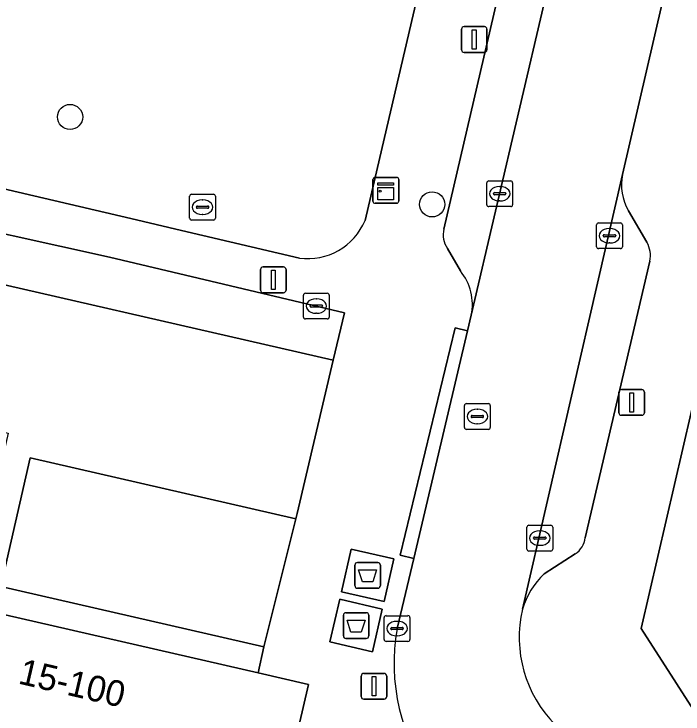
# Model space of a CAD drawing. Extents: x 161798 to 162385, y 382315 to 382833.
# Drawn here: x 161869.31 to 161895.31, y 382603.74 to 382630.93 of the extents above; entities that cross this region are included whole.
import ezdxf

# ---------------------------------------------------------------- set-up
doc = ezdxf.new("R2010")
doc.units = 0
for name, color, linetype in [('IMGEO_Afval_apart_plaats', 7, 'Continuous'), ('IMGEO_Boom', 7, 'Continuous'), ('IMGEO_Groenvoorziening', 7, 'Continuous'), ('IMGEO_Kast', 7, 'Continuous'), ('IMGEO_Kolk', 7, 'Continuous'), ('IMGEO_Lichtmast', 7, 'Continuous'), ('IMGEO_Pand', 7, 'Continuous'), ('IMGEO_Pand_nummerreeks', 7, 'Continuous'), ('IMGEO_Parkeervlak_open', 7, 'Continuous'), ('IMGEO_Rijbaan_lokaal_open', 7, 'Continuous'), ('IMGEO_Rioolput', 7, 'Continuous'), ('IMGEO_Voetpad_gesloten', 7, 'Continuous'), ('IMGEO_Voetpad_open', 7, 'Continuous')]:
    doc.layers.add(name, color=color, linetype=linetype)

msp = doc.modelspace()

# ---------------------------------------------------------------- linework, layer by layer
at = {"layer": 'IMGEO_Afval_apart_plaats'}
for p, q in [((161882.656, 382609.623), (161883.446, 382609.623)), ((161883.446, 382609.623), (161882.656, 382609.623)), ((161882.556, 382608.723), (161882.556, 382609.523)), ((161882.556, 382609.523), (161882.556, 382608.723)), ((161883.546, 382609.523), (161883.546, 382608.723)), ((161883.546, 382608.723), (161883.546, 382609.523)), ((161883.446, 382608.623), (161882.656, 382608.623)), ((161882.656, 382608.623), (161883.446, 382608.623)), ((161882.209, 382607.673), (161882.999, 382607.673)), ((161882.999, 382607.673), (161882.209, 382607.673)), ((161882.109, 382606.773), (161882.109, 382607.573)), ((161882.109, 382607.573), (161882.109, 382606.773)), ((161883.099, 382607.573), (161883.099, 382606.773)), ((161883.099, 382606.773), (161883.099, 382607.573)), ((161882.999, 382606.673), (161882.209, 382606.673)), ((161882.209, 382606.673), (161882.999, 382606.673))]:
    msp.add_line(p, q, dxfattribs=at)
for points in [[(161882.699, 382609.337), (161883.403, 382609.337), (161883.254, 382608.867), (161882.848, 382608.867), (161882.699, 382609.337)], [(161882.252, 382607.387), (161882.956, 382607.387), (161882.807, 382606.917), (161882.401, 382606.917), (161882.252, 382607.387)]]:
    msp.add_lwpolyline(points, dxfattribs=at)
for centre, start, end in [((161882.656, 382609.523), 90, 180), ((161882.656, 382609.523), 90, 180), ((161883.446, 382609.523), 0, 90), ((161883.446, 382609.523), 360, 90), ((161882.656, 382608.723), 180, 270), ((161882.656, 382608.723), 180, 270), ((161883.446, 382608.723), 270, 0), ((161883.446, 382608.723), 270, 0), ((161882.209, 382607.573), 90, 180), ((161882.209, 382607.573), 90, 180), ((161882.999, 382607.573), 0, 90), ((161882.999, 382607.573), 360, 90), ((161882.209, 382606.773), 180, 270), ((161882.209, 382606.773), 180, 270), ((161882.999, 382606.773), 270, 0), ((161882.999, 382606.773), 270, 0)]:
    msp.add_arc(centre, 0.1, start, end, dxfattribs=at)
at = {"layer": 'IMGEO_Boom'}
for centre in [(161871.49, 382626.931), (161885.558, 382623.535)]:
    msp.add_circle(centre, 0.489, dxfattribs=at)
at = {"layer": 'IMGEO_Groenvoorziening'}
for points in [[(161882.951, 382622.911), (161883.615, 382625.75), (161886.351, 382637.454), (161889.888, 382652.585)], [(161866.576, 382633.64), (161864.615, 382625.149), (161866.712, 382624.656), (161867.078, 382624.57), (161873.854, 382622.982), (161875.823, 382622.52), (161880.4, 382621.447)]]:
    msp.add_lwpolyline(points, dxfattribs=at)
msp.add_arc((161880.725, 382623.835), 2.41, 262.2536, 337.4488, dxfattribs=at)
at = {"layer": 'IMGEO_Kast'}
for p, q in [((161883.335, 382624.58), (161884.176, 382624.58)), ((161884.176, 382624.58), (161883.335, 382624.58)), ((161883.26, 382623.655), (161883.26, 382624.496)), ((161883.26, 382624.496), (161883.26, 382623.655)), ((161884.26, 382624.505), (161884.26, 382623.664)), ((161884.26, 382623.664), (161884.26, 382624.505)), ((161884.185, 382623.58), (161883.344, 382623.58)), ((161883.344, 382623.58), (161884.185, 382623.58))]:
    msp.add_line(p, q, dxfattribs=at)
for points in [[(161883.455, 382624.37), (161884.055, 382624.37), (161884.055, 382624.285), (161883.455, 382624.285), (161883.455, 382624.37)], [(161883.455, 382624.195), (161884.055, 382624.195), (161884.055, 382623.706), (161883.455, 382623.706), (161883.455, 382624.195)]]:
    msp.add_lwpolyline(points, dxfattribs=at)
msp.add_circle((161883.539, 382624.044), 0.0377, dxfattribs=at)
for centre, start, end in [((161883.338, 382624.502), 92.4484, 184.2845), ((161883.338, 382624.502), 92.4484, 184.2845), ((161884.182, 382624.502), 2.4484, 94.2845), ((161884.182, 382624.502), 2.4484, 94.2845), ((161883.338, 382623.658), 182.4484, 274.2845), ((161883.338, 382623.658), 182.4484, 274.2845), ((161884.182, 382623.658), 272.4484, 4.2845), ((161884.182, 382623.658), 272.4484, 4.2845)]:
    msp.add_arc(centre, 0.0779, start, end, dxfattribs=at)
at = {"layer": 'IMGEO_Kolk'}
for p, q in [((161887.684, 382623.521), (161887.684, 382624.373)), ((161887.759, 382624.447), (161888.611, 382624.447)), ((161888.685, 382624.373), (161888.685, 382623.521)), ((161887.986, 382623.99), (161888.384, 382623.99)), ((161888.172, 382624.227), (161888.197, 382624.227)), ((161887.943, 382623.941), (161887.943, 382623.953)), ((161888.381, 382623.904), (161887.983, 382623.904)), ((161888.427, 382623.953), (161888.427, 382623.941)), ((161888.611, 382623.447), (161887.759, 382623.447)), ((161888.195, 382623.667), (161888.17, 382623.667)), ((161891.952, 382621.888), (161891.952, 382622.74)), ((161892.027, 382622.814), (161892.879, 382622.814)), ((161892.953, 382622.74), (161892.953, 382621.888)), ((161892.254, 382622.357), (161892.652, 382622.357)), ((161892.44, 382622.594), (161892.465, 382622.594)), ((161892.211, 382622.308), (161892.211, 382622.32)), ((161892.649, 382622.271), (161892.251, 382622.271)), ((161892.695, 382622.32), (161892.695, 382622.308)), ((161892.879, 382621.814), (161892.027, 382621.814)), ((161892.463, 382622.034), (161892.438, 382622.034)), ((161880.558, 382619.157), (161880.558, 382620.009)), ((161880.633, 382620.083), (161881.485, 382620.083)), ((161881.559, 382620.009), (161881.559, 382619.157)), ((161880.86, 382619.626), (161881.258, 382619.626)), ((161881.046, 382619.863), (161881.071, 382619.863)), ((161880.817, 382619.577), (161880.817, 382619.589)), ((161881.255, 382619.54), (161880.857, 382619.54)), ((161881.301, 382619.589), (161881.301, 382619.577)), ((161881.485, 382619.083), (161880.633, 382619.083)), ((161881.069, 382619.303), (161881.044, 382619.303)), ((161889.244, 382610.143), (161889.244, 382610.995)), ((161889.319, 382611.069), (161890.171, 382611.069)), ((161890.245, 382610.995), (161890.245, 382610.143)), ((161889.732, 382610.849), (161889.757, 382610.849)), ((161889.503, 382610.563), (161889.503, 382610.575)), ((161889.941, 382610.526), (161889.543, 382610.526)), ((161889.546, 382610.612), (161889.944, 382610.612)), ((161889.987, 382610.575), (161889.987, 382610.563)), ((161889.755, 382610.289), (161889.73, 382610.289)), ((161890.171, 382610.069), (161889.319, 382610.069)), ((161883.694, 382606.631), (161883.694, 382607.483)), ((161883.769, 382607.557), (161884.621, 382607.557)), ((161884.695, 382607.483), (161884.695, 382606.631)), ((161884.182, 382607.337), (161884.207, 382607.337)), ((161883.953, 382607.051), (161883.953, 382607.063)), ((161884.391, 382607.014), (161883.993, 382607.014)), ((161883.996, 382607.1), (161884.394, 382607.1)), ((161884.437, 382607.063), (161884.437, 382607.051)), ((161884.205, 382606.777), (161884.18, 382606.777)), ((161884.621, 382606.557), (161883.769, 382606.557))]:
    msp.add_line(p, q, dxfattribs=at)
for points in [[(161887.684, 382623.521), (161887.684, 382624.373)], [(161887.759, 382624.447), (161888.611, 382624.447)], [(161888.685, 382624.373), (161888.685, 382623.521)], [(161888.611, 382623.447), (161887.759, 382623.447)], [(161891.952, 382621.888), (161891.952, 382622.74)], [(161892.027, 382622.814), (161892.879, 382622.814)], [(161892.953, 382622.74), (161892.953, 382621.888)], [(161892.879, 382621.814), (161892.027, 382621.814)], [(161880.558, 382619.157), (161880.558, 382620.009)], [(161880.633, 382620.083), (161881.485, 382620.083)], [(161881.559, 382620.009), (161881.559, 382619.157)], [(161881.485, 382619.083), (161880.633, 382619.083)], [(161889.244, 382610.143), (161889.244, 382610.995)], [(161889.319, 382611.069), (161890.171, 382611.069)], [(161890.245, 382610.995), (161890.245, 382610.143)], [(161890.171, 382610.069), (161889.319, 382610.069)], [(161883.694, 382606.631), (161883.694, 382607.483)], [(161883.769, 382607.557), (161884.621, 382607.557)], [(161884.695, 382607.483), (161884.695, 382606.631)], [(161884.621, 382606.557), (161883.769, 382606.557)]]:
    msp.add_lwpolyline(points, dxfattribs=at)
for centre, radius, start, end in [((161887.761, 382624.371), 0.0765, 91.552, 178.448), ((161887.761, 382624.371), 0.0765, 91.552, 178.448), ((161888.609, 382624.371), 0.0765, 1.552, 88.448), ((161888.609, 382624.371), 0.0765, 1.552, 88.448), ((161887.983, 382623.95), 0.0403, 85.8775, 175.7526), ((161888.388, 382623.952), 0.0386, 1.7309, 96.639), ((161887.98, 382623.94), 0.0366, 178.938, 274.7102), ((161888.384, 382623.947), 0.043, 264.8664, 352.4533), ((161887.761, 382623.523), 0.0765, 181.552, 268.448), ((161887.761, 382623.523), 0.0765, 181.552, 268.448), ((161888.609, 382623.523), 0.0765, 271.552, 358.448), ((161888.609, 382623.523), 0.0765, 271.552, 358.448), ((161892.029, 382622.738), 0.0765, 91.552, 178.448), ((161892.029, 382622.738), 0.0765, 91.552, 178.448), ((161892.877, 382622.738), 0.0765, 1.552, 88.448), ((161892.877, 382622.738), 0.0765, 1.552, 88.448), ((161892.251, 382622.317), 0.0403, 85.8775, 175.7526), ((161892.656, 382622.319), 0.0386, 1.7309, 96.639), ((161892.248, 382622.307), 0.0366, 178.938, 274.7102), ((161892.652, 382622.314), 0.043, 264.8664, 352.4533), ((161892.029, 382621.89), 0.0765, 181.552, 268.448), ((161892.029, 382621.89), 0.0765, 181.552, 268.448), ((161892.877, 382621.89), 0.0765, 271.552, 358.448), ((161892.877, 382621.89), 0.0765, 271.552, 358.448), ((161880.635, 382620.007), 0.0765, 91.552, 178.448), ((161880.635, 382620.007), 0.0765, 91.552, 178.448), ((161881.483, 382620.007), 0.0765, 1.552, 88.448), ((161881.483, 382620.007), 0.0765, 1.552, 88.448), ((161880.857, 382619.586), 0.0403, 85.8775, 175.7526), ((161881.262, 382619.588), 0.0386, 1.7309, 96.639), ((161880.854, 382619.576), 0.0366, 178.938, 274.7102), ((161881.258, 382619.583), 0.043, 264.8664, 352.4533), ((161880.635, 382619.159), 0.0765, 181.552, 268.448), ((161880.635, 382619.159), 0.0765, 181.552, 268.448), ((161881.483, 382619.159), 0.0765, 271.552, 358.448), ((161881.483, 382619.159), 0.0765, 271.552, 358.448), ((161889.321, 382610.993), 0.0765, 91.552, 178.448), ((161889.321, 382610.993), 0.0765, 91.552, 178.448), ((161890.169, 382610.993), 0.0765, 1.552, 88.448), ((161890.169, 382610.993), 0.0765, 1.552, 88.448), ((161889.543, 382610.572), 0.0403, 85.8775, 175.7526), ((161889.54, 382610.562), 0.0366, 178.938, 274.7102), ((161889.944, 382610.569), 0.043, 264.8664, 352.4533), ((161889.948, 382610.574), 0.0386, 1.7309, 96.639), ((161889.321, 382610.145), 0.0765, 181.552, 268.448), ((161889.321, 382610.145), 0.0765, 181.552, 268.448), ((161890.169, 382610.145), 0.0765, 271.552, 358.448), ((161890.169, 382610.145), 0.0765, 271.552, 358.448), ((161883.771, 382607.481), 0.0765, 91.552, 178.448), ((161883.771, 382607.481), 0.0765, 91.552, 178.448), ((161884.619, 382607.481), 0.0765, 1.552, 88.448), ((161884.619, 382607.481), 0.0765, 1.552, 88.448), ((161883.993, 382607.06), 0.0403, 85.8775, 175.7526), ((161883.99, 382607.05), 0.0366, 178.938, 274.7102), ((161884.394, 382607.057), 0.043, 264.8664, 352.4533), ((161884.398, 382607.062), 0.0386, 1.7309, 96.639), ((161883.771, 382606.633), 0.0765, 181.552, 268.448), ((161883.771, 382606.633), 0.0765, 181.552, 268.448), ((161884.619, 382606.633), 0.0765, 271.552, 358.448), ((161884.619, 382606.633), 0.0765, 271.552, 358.448)]:
    msp.add_arc(centre, radius, start, end, dxfattribs=at)
for centre, major_axis, ratio, start_param, end_param in [((161888.171, 382623.947), (-0.387, 0.002), 0.722429, 4.712389, 7.853982), ((161888.196, 382623.947), (-0.39, 0.002), 0.717154, 1.570796, 4.712389), ((161892.439, 382622.314), (-0.387, 0.002), 0.722429, 4.712389, 7.853982), ((161892.464, 382622.314), (-0.39, 0.002), 0.717154, 1.570796, 4.712389), ((161881.045, 382619.583), (-0.387, 0.002), 0.722429, 4.712389, 7.853982), ((161881.07, 382619.583), (-0.39, 0.002), 0.717154, 1.570796, 4.712389), ((161889.731, 382610.569), (-0.387, 0.002), 0.722429, 4.712389, 7.853982), ((161889.756, 382610.569), (-0.39, 0.002), 0.717154, 1.570796, 4.712389), ((161884.181, 382607.057), (-0.387, 0.002), 0.722429, 4.712389, 7.853982), ((161884.206, 382607.057), (-0.39, 0.002), 0.717154, 1.570796, 4.712389)]:
    msp.add_ellipse(centre, major_axis=major_axis, ratio=ratio, start_param=start_param, end_param=end_param, dxfattribs=at)
at = {"layer": 'IMGEO_Lichtmast'}
for p, q in [((161886.699, 382629.54), (161886.699, 382630.34)), ((161886.699, 382630.34), (161886.699, 382629.54)), ((161886.799, 382630.44), (161887.589, 382630.44)), ((161887.589, 382630.44), (161886.799, 382630.44)), ((161887.689, 382630.34), (161887.689, 382629.54)), ((161887.689, 382629.54), (161887.689, 382630.34)), ((161887.589, 382629.44), (161886.799, 382629.44)), ((161886.799, 382629.44), (161887.589, 382629.44)), ((161878.891, 382620.202), (161878.891, 382621.002)), ((161878.891, 382621.002), (161878.891, 382620.202)), ((161878.991, 382621.102), (161879.781, 382621.102)), ((161879.781, 382621.102), (161878.991, 382621.102)), ((161879.881, 382621.002), (161879.881, 382620.202)), ((161879.881, 382620.202), (161879.881, 382621.002)), ((161879.781, 382620.102), (161878.991, 382620.102)), ((161878.991, 382620.102), (161879.781, 382620.102)), ((161892.816, 382615.441), (161892.816, 382616.241)), ((161892.816, 382616.241), (161892.816, 382615.441)), ((161892.916, 382616.341), (161893.706, 382616.341)), ((161893.706, 382616.341), (161892.916, 382616.341)), ((161893.806, 382616.241), (161893.806, 382615.441)), ((161893.806, 382615.441), (161893.806, 382616.241)), ((161893.706, 382615.341), (161892.916, 382615.341)), ((161892.916, 382615.341), (161893.706, 382615.341)), ((161882.803, 382604.413), (161882.803, 382605.213)), ((161882.803, 382605.213), (161882.803, 382604.413)), ((161882.903, 382605.313), (161883.693, 382605.313)), ((161883.693, 382605.313), (161882.903, 382605.313)), ((161883.793, 382605.213), (161883.793, 382604.413)), ((161883.793, 382604.413), (161883.793, 382605.213)), ((161883.693, 382604.313), (161882.903, 382604.313)), ((161882.903, 382604.313), (161883.693, 382604.313))]:
    msp.add_line(p, q, dxfattribs=at)
for points in [[(161887.119, 382630.315), (161887.269, 382630.315), (161887.269, 382629.565), (161887.119, 382629.565), (161887.119, 382630.315)], [(161879.311, 382620.977), (161879.461, 382620.977), (161879.461, 382620.227), (161879.311, 382620.227), (161879.311, 382620.977)], [(161893.236, 382616.216), (161893.386, 382616.216), (161893.386, 382615.466), (161893.236, 382615.466), (161893.236, 382616.216)], [(161883.223, 382605.188), (161883.373, 382605.188), (161883.373, 382604.438), (161883.223, 382604.438), (161883.223, 382605.188)]]:
    msp.add_lwpolyline(points, dxfattribs=at)
for centre, start, end in [((161886.799, 382630.34), 90, 180), ((161886.799, 382630.34), 90, 180), ((161887.589, 382630.34), 0, 90), ((161887.589, 382630.34), 360, 90), ((161886.799, 382629.54), 180, 270), ((161886.799, 382629.54), 180, 270), ((161887.589, 382629.54), 270, 0), ((161887.589, 382629.54), 270, 0), ((161878.991, 382621.002), 90, 180), ((161878.991, 382621.002), 90, 180), ((161879.781, 382621.002), 0, 90), ((161879.781, 382621.002), 360, 90), ((161878.991, 382620.202), 180, 270), ((161878.991, 382620.202), 180, 270), ((161879.781, 382620.202), 270, 0), ((161879.781, 382620.202), 270, 0), ((161892.916, 382616.241), 90, 180), ((161892.916, 382616.241), 90, 180), ((161893.706, 382616.241), 0, 90), ((161893.706, 382616.241), 360, 90), ((161892.916, 382615.441), 180, 270), ((161892.916, 382615.441), 180, 270), ((161893.706, 382615.441), 270, 0), ((161893.706, 382615.441), 270, 0), ((161882.903, 382605.213), 90, 180), ((161882.903, 382605.213), 90, 180), ((161883.693, 382605.213), 0, 90), ((161883.693, 382605.213), 360, 90), ((161882.903, 382604.413), 180, 270), ((161882.903, 382604.413), 180, 270), ((161883.693, 382604.413), 270, 0), ((161883.693, 382604.413), 270, 0)]:
    msp.add_arc(centre, 0.1, start, end, dxfattribs=at)
at = {"layer": 'IMGEO_Pand'}
for points in [[(161905.177, 382608.439), (161905.03, 382608.666), (161904.891, 382609.807), (161905.656, 382613.133), (161895.622, 382615.453), (161893.679, 382607.053), (161896.429, 382602.791)], [(161880.75, 382604.884), (161878.792, 382605.334), (161867.541, 382607.918), (161867.413, 382607.947), (161867.021, 382606.239), (161864.082, 382606.914), (161864.488, 382608.68), (161861.243, 382609.426), (161854.417, 382610.994), (161848.273, 382584.466), (161874.618, 382578.415), (161876.31, 382585.719), (161876.316, 382585.744)]]:
    msp.add_lwpolyline(points, close=True, dxfattribs=at)
at = {"layer": 'IMGEO_Parkeervlak_open'}
for points in [[(161887.081, 382619.224), (161894.64, 382651.564)], [(161892.144, 382648.916), (161886.018, 382622.573)], [(161892.955, 382624.701), (161889.072, 382607.805)], [(161893.907, 382622.06), (161893.191, 382623.288)], [(161886.15, 382621.821), (161886.661, 382620.948)], [(161891.512, 382610.583), (161894.021, 382621.331)], [(161889.911, 382609.185), (161891.118, 382609.954)]]:
    msp.add_lwpolyline(points, dxfattribs=at)
for points in [[(161865.4, 382623.168), (161864.975, 382621.309), (161881.719, 382617.477), (161882.157, 382619.325), (161873.025, 382621.478)], [(161880.256, 382611.317), (161869.944, 382613.686), (161868.797, 382608.696), (161879.024, 382606.347)]]:
    msp.add_lwpolyline(points, close=True, dxfattribs=at)
for centre, radius, start, end in [((161894.943, 382624.307), 2.027, 168.7879, 210.1762), ((161886.928, 382622.345), 0.938, 165.935, 213.9767), ((161892.991, 382621.543), 1.052, 348.3528, 29.4229), ((161885.062, 382619.645), 2.062, 348.2128, 39.1705), ((161890.634, 382610.695), 0.885, 303.1449, 352.7298), ((161892.043, 382606.944), 3.093, 133.5671, 163.8362)]:
    msp.add_arc(centre, radius, start, end, dxfattribs=at)
at = {"layer": 'IMGEO_Rijbaan_lokaal_open'}
for points in [[(161945.213, 382710.416), (161928.944, 382695.23), (161927.839, 382694.207), (161923.279, 382689.986), (161922.425, 382689.194), (161900.203, 382668.529), (161899.049, 382666.462), (161898.991, 382666.31), (161898.831, 382666.002), (161898.479, 382665.384), (161897.396, 382663.481), (161895.017, 382652.922), (161894.863, 382652.591), (161894.64, 382651.564), (161887.081, 382619.224), (161886.935, 382618.622), (161884.842, 382609.776), (161884.196, 382607.053)], [(161892.955, 382624.701), (161898.518, 382648.702), (161899.388, 382652.453), (161901.884, 382663.119), (161901.973, 382663.501)], [(161889.072, 382607.805), (161892.955, 382624.701)]]:
    msp.add_lwpolyline(points, dxfattribs=at)
msp.add_lwpolyline([(161864.975, 382621.309), (161865.4, 382623.168), (161864.218, 382623.43), (161864.615, 382625.149), (161866.576, 382633.64), (161871.857, 382656.486), (161867.395, 382657.47), (161856.759, 382611.458), (161861.462, 382610.378), (161862.775, 382616.091), (161869.085, 382614.642), (161867.774, 382608.931), (161868.797, 382608.696), (161869.944, 382613.686), (161880.256, 382611.317), (161880.309, 382611.531), (161881.719, 382617.477)], close=True, dxfattribs=at)
for centre, radius, start, end in [((161893.744, 382606.706), 4.8, 166.7603, 224.8604), ((161891.8, 382605.707), 7.722, 169.96, 216.3203)]:
    msp.add_arc(centre, radius, start, end, dxfattribs=at)
at = {"layer": 'IMGEO_Rioolput'}
for p, q in [((161876.136, 382623), (161876.136, 382623.852)), ((161876.211, 382623.926), (161877.063, 382623.926)), ((161876.624, 382623.706), (161876.649, 382623.706)), ((161877.137, 382623.852), (161877.137, 382623)), ((161876.395, 382623.42), (161876.395, 382623.432)), ((161876.438, 382623.469), (161876.836, 382623.469)), ((161876.879, 382623.432), (161876.879, 382623.42)), ((161876.833, 382623.383), (161876.435, 382623.383)), ((161877.063, 382622.926), (161876.211, 382622.926)), ((161876.647, 382623.146), (161876.622, 382623.146)), ((161886.816, 382614.868), (161886.816, 382615.72)), ((161886.891, 382615.794), (161887.743, 382615.794)), ((161887.304, 382615.574), (161887.329, 382615.574)), ((161887.817, 382615.72), (161887.817, 382614.868)), ((161887.075, 382615.288), (161887.075, 382615.3)), ((161887.118, 382615.337), (161887.516, 382615.337)), ((161887.559, 382615.3), (161887.559, 382615.288)), ((161887.513, 382615.251), (161887.115, 382615.251)), ((161887.327, 382615.014), (161887.302, 382615.014)), ((161887.743, 382614.794), (161886.891, 382614.794))]:
    msp.add_line(p, q, dxfattribs=at)
for points in [[(161876.136, 382623), (161876.136, 382623.852)], [(161876.211, 382623.926), (161877.063, 382623.926)], [(161877.137, 382623.852), (161877.137, 382623)], [(161877.063, 382622.926), (161876.211, 382622.926)], [(161886.816, 382614.868), (161886.816, 382615.72)], [(161886.891, 382615.794), (161887.743, 382615.794)], [(161887.817, 382615.72), (161887.817, 382614.868)], [(161887.743, 382614.794), (161886.891, 382614.794)]]:
    msp.add_lwpolyline(points, dxfattribs=at)
for centre, radius, start, end in [((161876.213, 382623.85), 0.0765, 91.552, 178.448), ((161876.213, 382623.85), 0.0765, 91.552, 178.448), ((161877.061, 382623.85), 0.0765, 1.552, 88.448), ((161877.061, 382623.85), 0.0765, 1.552, 88.448), ((161876.435, 382623.429), 0.0403, 85.8775, 175.7526), ((161876.432, 382623.419), 0.0366, 178.938, 274.7102), ((161876.836, 382623.426), 0.043, 264.8664, 352.4533), ((161876.84, 382623.431), 0.0386, 1.7309, 96.639), ((161876.213, 382623.002), 0.0765, 181.552, 268.448), ((161876.213, 382623.002), 0.0765, 181.552, 268.448), ((161877.061, 382623.002), 0.0765, 271.552, 358.448), ((161877.061, 382623.002), 0.0765, 271.552, 358.448), ((161886.893, 382615.718), 0.0765, 91.552, 178.448), ((161886.893, 382615.718), 0.0765, 91.552, 178.448), ((161887.741, 382615.718), 0.0765, 1.552, 88.448), ((161887.741, 382615.718), 0.0765, 1.552, 88.448), ((161887.115, 382615.297), 0.0403, 85.8775, 175.7526), ((161887.112, 382615.287), 0.0366, 178.938, 274.7102), ((161887.516, 382615.294), 0.043, 264.8664, 352.4533), ((161887.52, 382615.299), 0.0386, 1.7309, 96.639), ((161886.893, 382614.87), 0.0765, 181.552, 268.448), ((161886.893, 382614.87), 0.0765, 181.552, 268.448), ((161887.741, 382614.87), 0.0765, 271.552, 358.448), ((161887.741, 382614.87), 0.0765, 271.552, 358.448)]:
    msp.add_arc(centre, radius, start, end, dxfattribs=at)
for centre, major_axis, ratio, start_param, end_param in [((161876.623, 382623.426), (-0.387, 0.002), 0.722429, 4.712389, 7.853982), ((161876.648, 382623.426), (-0.39, 0.002), 0.717154, 1.570796, 4.712389), ((161887.303, 382615.294), (-0.387, 0.002), 0.722429, 4.712389, 7.853982), ((161887.328, 382615.294), (-0.39, 0.002), 0.717154, 1.570796, 4.712389)]:
    msp.add_ellipse(centre, major_axis=major_axis, ratio=ratio, start_param=start_param, end_param=end_param, dxfattribs=at)
at = {"layer": 'IMGEO_Voetpad_gesloten'}
for points in [[(161884.068, 382609.761), (161882.411, 382610.142), (161882.033, 382608.485), (161883.69, 382608.104)], [(161883.622, 382607.812), (161881.966, 382608.192), (161881.587, 382606.535), (161883.242, 382606.155)]]:
    msp.add_lwpolyline(points, close=True, dxfattribs=at)
at = {"layer": 'IMGEO_Voetpad_open'}
for points in [[(161893.679, 382607.053), (161895.622, 382615.453), (161897.228, 382622.395), (161898.755, 382628.994), (161900.274, 382635.56), (161901.764, 382642), (161903.26, 382648.466), (161903.677, 382650.27), (161903.793, 382650.769), (161905.406, 382657.742), (161906.786, 382663.708), (161902.673, 382665.26)], [(161891.148, 382656.909), (161890.901, 382655.706), (161889.888, 382652.585), (161886.351, 382637.454), (161883.615, 382625.75), (161882.951, 382622.911)], [(161899.388, 382652.453), (161899.851, 382652.271), (161899.011, 382648.59), (161898.518, 382648.702), (161892.955, 382624.701)], [(161886.018, 382622.573), (161892.144, 382648.916)], [(161880.4, 382621.447), (161875.823, 382622.52), (161873.854, 382622.982), (161867.078, 382624.57), (161866.712, 382624.656), (161864.615, 382625.149), (161864.218, 382623.43), (161865.4, 382623.168), (161873.025, 382621.478), (161882.157, 382619.325), (161881.719, 382617.477), (161880.309, 382611.531), (161880.256, 382611.317), (161879.024, 382606.347), (161878.792, 382605.334), (161880.75, 382604.884), (161876.316, 382585.744)], [(161893.191, 382623.288), (161893.907, 382622.06)], [(161886.661, 382620.948), (161886.15, 382621.821)], [(161894.021, 382621.331), (161891.512, 382610.583)], [(161884.196, 382607.053), (161884.842, 382609.776), (161884.315, 382609.903), (161886.449, 382618.739), (161886.935, 382618.622), (161887.081, 382619.224)], [(161891.118, 382609.954), (161889.911, 382609.185)], [(161913.355, 382577.804), (161911.109, 382580.039), (161907.448, 382585.713), (161903.859, 382591.275), (161900.195, 382596.954), (161896.429, 382602.791), (161893.679, 382607.053)]]:
    msp.add_lwpolyline(points, dxfattribs=at)
for points in [[(161884.842, 382609.776), (161886.935, 382618.622), (161886.449, 382618.739), (161884.315, 382609.903)], [(161854.643, 382611.944), (161854.625, 382611.948), (161854.417, 382610.994), (161861.243, 382609.426), (161864.488, 382608.68), (161867.413, 382607.947), (161867.541, 382607.918), (161878.792, 382605.334), (161879.024, 382606.347), (161868.797, 382608.696), (161867.774, 382608.931), (161861.462, 382610.378), (161856.759, 382611.458)], [(161884.068, 382609.761), (161883.69, 382608.104), (161882.033, 382608.485), (161882.411, 382610.142)], [(161883.622, 382607.812), (161883.242, 382606.155), (161881.587, 382606.535), (161881.966, 382608.192)]]:
    msp.add_lwpolyline(points, close=True, dxfattribs=at)
for centre, radius, start, end in [((161894.943, 382624.307), 2.027, 168.7879, 210.1762), ((161880.725, 382623.835), 2.41, 262.2536, 337.4488), ((161886.928, 382622.345), 0.938, 165.935, 213.9767), ((161892.991, 382621.543), 1.052, 348.3528, 29.4229), ((161885.062, 382619.645), 2.062, 348.2128, 39.1705), ((161890.634, 382610.695), 0.885, 303.1449, 352.7298), ((161892.043, 382606.944), 3.093, 133.5671, 163.8362), ((161893.744, 382606.706), 4.8, 166.7603, 224.8604), ((161891.8, 382605.707), 7.722, 169.96, 216.3203)]:
    msp.add_arc(centre, radius, start, end, dxfattribs=at)

# ---------------------------------------------------------------- texts
at = {"layer": 'IMGEO_Pand_nummerreeks'}
msp.add_text('15-100', height=1, rotation=346.8678, dxfattribs=at).set_placement((161869.435, 382604.928))

doc.saveas('drawing.dxf')
